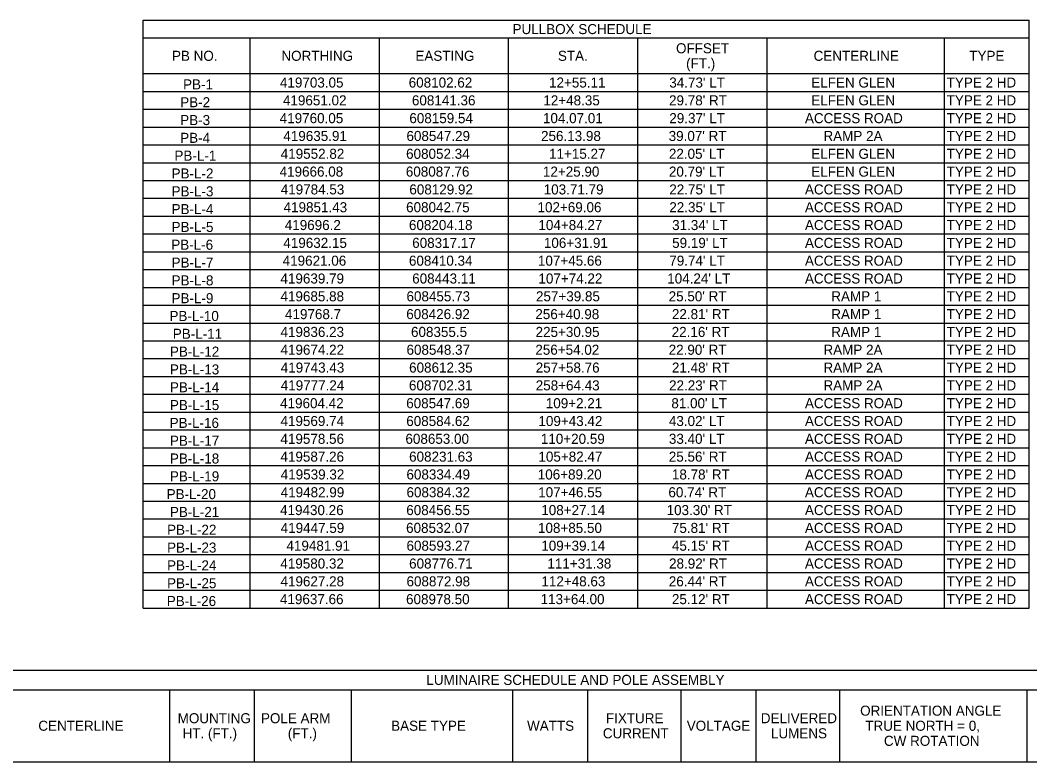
# Model space of a CAD drawing. Extents: x 0.17 to 2.79, y 0.05 to 1.72.
# Drawn here: x 0.862 to 1.859, y 0.976 to 1.708 of the extents above; entities that cross this region are included whole.
import ezdxf

# ---------------------------------------------------------------- set-up
doc = ezdxf.new("R2010")
doc.units = 0
doc.layers.add('Default', color=7, linetype='Continuous')
doc.layers.add('No_Plot', color=7, linetype='Continuous')

msp = doc.modelspace()

# ---------------------------------------------------------------- linework, layer by layer
at = {"layer": 'Default'}
for p, q in [((0.98367, 1.70829), (1.85833, 1.70829)), ((0.98367, 1.12753), (0.98367, 1.70829)), ((1.85833, 1.12753), (1.85833, 1.70829)), ((0.98367, 1.69069), (1.85833, 1.69069)), ((1.08927, 1.12753), (1.08927, 1.69069)), ((1.21686, 1.12753), (1.21686, 1.69069)), ((1.34445, 1.12753), (1.34445, 1.69069)), ((1.47204, 1.12753), (1.47204, 1.69069)), ((1.59963, 1.12753), (1.59963, 1.69069)), ((1.77474, 1.12753), (1.77474, 1.69069)), ((0.98367, 1.65549), (1.85833, 1.65549)), ((0.98367, 1.63789), (1.85833, 1.63789)), ((0.98367, 1.6203), (1.85833, 1.6203)), ((0.98367, 1.6027), (1.85833, 1.6027)), ((0.98367, 1.5851), (1.85833, 1.5851)), ((0.98367, 1.5675), (1.85833, 1.5675)), ((0.98367, 1.5499), (1.85833, 1.5499)), ((0.98367, 1.5323), (1.85833, 1.5323)), ((0.98367, 1.5147), (1.85833, 1.5147)), ((0.98367, 1.4971), (1.85833, 1.4971)), ((0.98367, 1.47951), (1.85833, 1.47951)), ((0.98367, 1.46191), (1.85833, 1.46191)), ((0.98367, 1.44431), (1.85833, 1.44431)), ((0.98367, 1.42671), (1.85833, 1.42671)), ((0.98367, 1.40911), (1.85833, 1.40911)), ((0.98367, 1.39151), (1.85833, 1.39151)), ((0.98367, 1.37391), (1.85833, 1.37391)), ((0.98367, 1.35631), (1.85833, 1.35631)), ((0.98367, 1.33872), (1.85833, 1.33872)), ((0.98367, 1.32112), (1.85833, 1.32112)), ((0.98367, 1.30352), (1.85833, 1.30352)), ((0.98367, 1.28592), (1.85833, 1.28592)), ((0.98367, 1.26832), (1.85833, 1.26832)), ((0.98367, 1.25072), (1.85833, 1.25072)), ((0.98367, 1.23312), (1.85833, 1.23312)), ((0.98367, 1.21552), (1.85833, 1.21552)), ((0.98367, 1.19793), (1.85833, 1.19793)), ((0.98367, 1.18033), (1.85833, 1.18033)), ((0.98367, 1.16273), (1.85833, 1.16273)), ((0.98367, 1.14513), (1.85833, 1.14513)), ((0.98367, 1.12753), (1.85833, 1.12753)), ((0.32609, 1.06625), (2.52066, 1.06625)), ((0.32609, 1.04689), (2.52066, 1.04689)), ((1.0098, 0.97562), (1.0098, 1.04689)), ((1.0934, 0.97562), (1.0934, 1.04689)), ((1.18931, 0.97562), (1.18931, 1.04689)), ((1.34858, 0.97562), (1.34858, 1.04689)), ((1.42249, 0.97562), (1.42249, 1.04689)), ((1.51489, 0.97562), (1.51489, 1.04689)), ((1.5888, 0.97562), (1.5888, 1.04689)), ((1.67152, 0.97562), (1.67152, 1.04689)), ((1.8563, 0.97562), (1.8563, 1.04689)), ((0.32609, 0.97562), (2.52066, 0.97562))]:
    msp.add_line(p, q, dxfattribs=at)
at = {"layer": 'No_Plot'}
msp.add_line((0.98367, 1.70829), (0.98367, 1.70829), dxfattribs=at)

# ---------------------------------------------------------------- texts
at = {"layer": 'Default'}
for s, height, p in [('PULLBOX SCHEDULE', 0.0099275, (1.34831, 1.69453)), ('OFFSET', 0.009927, (1.50969, 1.67557)), ('PB NO.', 0.009927, (1.01208, 1.66813)), ('NORTHING', 0.009927, (1.12011, 1.66813)), ('EASTING', 0.009927, (1.2524, 1.66813)), ('STA.', 0.009927, (1.39308, 1.66813)), ('CENTERLINE', 0.009927, (1.64552, 1.66813)), ('TYPE', 0.009927, (1.79918, 1.66813)), (' (FT.)', 0.009927, (1.51594, 1.66068)), ('PB-1', 0.009927, (1.02303, 1.63988)), ('419703.05', 0.009927, (1.11867, 1.64173)), ('608102.62', 0.009927, (1.24579, 1.64173)), ('12+55.11', 0.009927, (1.38432, 1.64173)), ("34.73' LT", 0.009927, (1.50304, 1.64173)), ('ELFEN GLEN', 0.009927, (1.64329, 1.64173)), ('TYPE 2 HD', 0.009927, (1.77686, 1.64173)), ('PB-2', 0.009927, (1.02021, 1.62228)), ('419651.02', 0.009927, (1.12164, 1.62413)), ('608141.36', 0.009927, (1.24896, 1.62413)), ('12+48.35', 0.009927, (1.3787, 1.62413)), ("29.78' RT", 0.009927, (1.50281, 1.62413)), ('ELFEN GLEN', 0.009927, (1.64329, 1.62413)), ('TYPE 2 HD', 0.009927, (1.77686, 1.62413)), ('PB-3', 0.009927, (1.02021, 1.60468)), ('419760.05', 0.009927, (1.11843, 1.60653)), ('608159.54', 0.009927, (1.24642, 1.60653)), ('104.07.01', 0.009927, (1.37831, 1.60653)), ("29.37' LT", 0.009927, (1.50304, 1.60653)), ('ACCESS ROAD', 0.0099275, (1.63696, 1.60653)), ('TYPE 2 HD', 0.009927, (1.77686, 1.60653)), ('PB-4', 0.009927, (1.02021, 1.58708)), ('419635.91', 0.009927, (1.12203, 1.58893)), ('608547.29', 0.009927, (1.24356, 1.58893)), ('256.13.98', 0.009927, (1.37643, 1.58893)), ("39.07' RT", 0.009927, (1.50242, 1.58893)), ('RAMP 2A', 0.009927, (1.65525, 1.58893)), ('TYPE 2 HD', 0.009927, (1.77686, 1.58893)), ('PB-L-1', 0.009927, (1.01451, 1.56948)), ('419552.82', 0.009927, (1.11945, 1.57134)), ('608052.34', 0.009927, (1.24321, 1.57134)), ('11+15.27', 0.009927, (1.38432, 1.57134)), ("22.05' LT", 0.009927, (1.50265, 1.57134)), ('ELFEN GLEN', 0.009927, (1.64329, 1.57134)), ('TYPE 2 HD', 0.009927, (1.77686, 1.57134)), ('PB-L-2', 0.009927, (1.01169, 1.55189)), ('419666.08', 0.009927, (1.11836, 1.55374)), ('608087.76', 0.009927, (1.24294, 1.55374)), ('12+25.90', 0.009927, (1.37827, 1.55374)), ("20.79' LT", 0.009927, (1.50265, 1.55374)), ('ELFEN GLEN', 0.009927, (1.64329, 1.55374)), ('TYPE 2 HD', 0.009927, (1.77686, 1.55374)), ('419784.53', 0.009927, (1.11945, 1.53614)), ('608129.92', 0.009927, (1.24642, 1.53614)), ('103.71.79', 0.009927, (1.37905, 1.53614)), ("22.75' LT", 0.009927, (1.50304, 1.53614)), ('ACCESS ROAD', 0.0099275, (1.63696, 1.53614)), ('TYPE 2 HD', 0.009927, (1.77686, 1.53614)), ('PB-L-3', 0.009927, (1.01169, 1.53429)), ('PB-L-4', 0.009927, (1.01169, 1.51669)), ('419851.43', 0.009927, (1.12226, 1.51854)), ('608042.75', 0.009927, (1.24321, 1.51854)), ('102+69.06', 0.009927, (1.37295, 1.51854)), ("22.35' LT", 0.009927, (1.50304, 1.51854)), ('ACCESS ROAD', 0.0099275, (1.63696, 1.51854)), ('TYPE 2 HD', 0.009927, (1.77686, 1.51854)), ('PB-L-5', 0.009927, (1.01169, 1.49909)), ('419696.2', 0.009927, (1.12344, 1.50094)), ('608204.18', 0.009927, (1.24602, 1.50094)), ('104+84.27', 0.009927, (1.37385, 1.50094)), ("31.34' LT", 0.009927, (1.50586, 1.50094)), ('ACCESS ROAD', 0.0099275, (1.63696, 1.50094)), ('TYPE 2 HD', 0.009927, (1.77686, 1.50094)), ('PB-L-6', 0.009927, (1.01142, 1.48149)), ('419632.15', 0.009927, (1.12203, 1.48334)), ('608317.17', 0.009927, (1.24923, 1.48334)), ('106+31.91', 0.009927, (1.37924, 1.48334)), ("59.19' LT", 0.009927, (1.50586, 1.48334)), ('ACCESS ROAD', 0.0099275, (1.63696, 1.48334)), ('TYPE 2 HD', 0.009927, (1.77686, 1.48334)), ('419621.06', 0.009927, (1.12136, 1.46574)), ('608410.34', 0.009927, (1.24602, 1.46574)), ('107+45.66', 0.009927, (1.37334, 1.46574)), ("79.74' LT", 0.009927, (1.50304, 1.46574)), ('ACCESS ROAD', 0.0099275, (1.63696, 1.46574)), ('TYPE 2 HD', 0.009927, (1.77686, 1.46574)), ('PB-L-7', 0.009927, (1.01169, 1.46389)), ('PB-L-8', 0.009927, (1.01169, 1.44629)), ('419639.79', 0.009927, (1.11918, 1.44814)), ('608443.11', 0.009927, (1.24923, 1.44814)), ('107+74.22', 0.009927, (1.37385, 1.44814)), ("104.24' LT", 0.009927, (1.50101, 1.44814)), ('ACCESS ROAD', 0.0099275, (1.63696, 1.44814)), ('TYPE 2 HD', 0.009927, (1.77686, 1.44814)), ('PB-L-9', 0.009927, (1.01165, 1.42869)), ('419685.88', 0.009927, (1.11921, 1.43055)), ('608455.73', 0.009927, (1.2436, 1.43055)), ('257+39.85', 0.009927, (1.37143, 1.43055)), ("25.50' RT", 0.009927, (1.50242, 1.43055)), ('RAMP 1', 0.009927, (1.66295, 1.43055)), ('TYPE 2 HD', 0.009927, (1.77686, 1.43055)), ('PB-L-10', 0.009927, (1.00962, 1.4111)), ('419768.7', 0.009927, (1.12367, 1.41295)), ('608426.92', 0.009927, (1.24337, 1.41295)), ('256+40.98', 0.009927, (1.3708, 1.41295)), ("22.81' RT", 0.009927, (1.50562, 1.41295)), ('RAMP 1', 0.009927, (1.66295, 1.41295)), ('TYPE 2 HD', 0.009927, (1.77686, 1.41295)), ('419836.23', 0.009927, (1.11921, 1.39535)), ('608355.5', 0.009927, (1.24806, 1.39535)), ('225+30.95', 0.009927, (1.37104, 1.39535)), ("22.16' RT", 0.009927, (1.50539, 1.39535)), ('TYPE 2 HD', 0.009927, (1.77686, 1.39535)), ('PB-L-11', 0.009927, (1.01286, 1.3935)), ('RAMP 1', 0.009927, (1.66295, 1.39535)), ('PB-L-12', 0.009927, (1.01005, 1.3759)), ('419674.22', 0.009927, (1.11921, 1.37775)), ('608548.37', 0.009927, (1.2436, 1.37775)), ('256+54.02', 0.009927, (1.3708, 1.37775)), ("22.90' RT", 0.009927, (1.50242, 1.37775)), ('RAMP 2A', 0.009927, (1.65525, 1.37775)), ('TYPE 2 HD', 0.009927, (1.77686, 1.37775)), ('PB-L-13', 0.009927, (1.01005, 1.3583)), ('419743.43', 0.009927, (1.11945, 1.36015)), ('608612.35', 0.009927, (1.24618, 1.36015)), ('257+58.76', 0.009927, (1.37115, 1.36015)), ("21.48' RT", 0.009927, (1.50562, 1.36015)), ('RAMP 2A', 0.009927, (1.65525, 1.36015)), ('TYPE 2 HD', 0.009927, (1.77686, 1.36015)), ('PB-L-14', 0.009927, (1.01005, 1.3407)), ('419777.24', 0.009927, (1.11945, 1.34255)), ('608702.31', 0.009927, (1.24602, 1.34255)), ('258+64.43', 0.009927, (1.37119, 1.34255)), ("22.23' RT", 0.009927, (1.50281, 1.34255)), ('RAMP 2A', 0.009927, (1.65525, 1.34255)), ('TYPE 2 HD', 0.009927, (1.77686, 1.34255)), ('PB-L-15', 0.009927, (1.01005, 1.3231)), ('419604.42', 0.009927, (1.11882, 1.32495)), ('608547.69', 0.009927, (1.24333, 1.32495)), ('109+2.21', 0.009927, (1.38112, 1.32495)), ("81.00' LT", 0.009927, (1.50508, 1.32495)), ('ACCESS ROAD', 0.0099275, (1.63696, 1.32495)), ('TYPE 2 HD', 0.009927, (1.77686, 1.32495)), ('419569.74', 0.009927, (1.11921, 1.30735)), ('608584.62', 0.009927, (1.24337, 1.30735)), ('109+43.42', 0.009927, (1.37385, 1.30735)), ("43.02' LT", 0.009927, (1.50265, 1.30735)), ('ACCESS ROAD', 0.0099275, (1.63696, 1.30735)), ('TYPE 2 HD', 0.009927, (1.77686, 1.30735)), ('PB-L-16', 0.009927, (1.00978, 1.3055)), ('PB-L-17', 0.009927, (1.01005, 1.2879)), ('419578.56', 0.009927, (1.11918, 1.28976)), ('608653.00', 0.009927, (1.24255, 1.28976)), ('110+20.59', 0.009927, (1.37623, 1.28976)), ("33.40' LT", 0.009927, (1.50265, 1.28976)), ('ACCESS ROAD', 0.0099275, (1.63696, 1.28976)), ('TYPE 2 HD', 0.009927, (1.77686, 1.28976)), ('PB-L-18', 0.009927, (1.01005, 1.27031)), ('419587.26', 0.009927, (1.11918, 1.27216)), ('608231.63', 0.009927, (1.24618, 1.27216)), ('105+82.47', 0.009927, (1.37385, 1.27216)), ("25.56' RT", 0.009927, (1.50257, 1.27216)), ('ACCESS ROAD', 0.0099275, (1.63696, 1.27216)), ('TYPE 2 HD', 0.009927, (1.77686, 1.27216)), ('PB-L-19', 0.009927, (1.01001, 1.25271)), ('419539.32', 0.009927, (1.11945, 1.25456)), ('608334.49', 0.009927, (1.24356, 1.25456)), ('106+89.20', 0.009927, (1.37319, 1.25456)), ("18.78' RT", 0.009927, (1.50562, 1.25456)), ('ACCESS ROAD', 0.0099275, (1.63696, 1.25456)), ('TYPE 2 HD', 0.009927, (1.77686, 1.25456)), ('419482.99', 0.009927, (1.11941, 1.23696)), ('608384.32', 0.009927, (1.2436, 1.23696)), ('107+46.55', 0.009927, (1.37362, 1.23696)), ("60.74' RT", 0.009927, (1.50218, 1.23696)), ('ACCESS ROAD', 0.0099275, (1.63696, 1.23696)), ('TYPE 2 HD', 0.009927, (1.77686, 1.23696)), ('PB-L-20', 0.009927, (1.00681, 1.23511)), ('PB-L-21', 0.009927, (1.01005, 1.21751)), ('419430.26', 0.009927, (1.11879, 1.21936)), ('608456.55', 0.009927, (1.24337, 1.21936)), ('108+27.14', 0.009927, (1.37666, 1.21936)), ("103.30' RT", 0.009927, (1.50039, 1.21936)), ('ACCESS ROAD', 0.0099275, (1.63696, 1.21936)), ('TYPE 2 HD', 0.009927, (1.77686, 1.21936)), ('PB-L-22', 0.009927, (1.00724, 1.19991)), ('419447.59', 0.009927, (1.11941, 1.20176)), ('608532.07', 0.009927, (1.24321, 1.20176)), ('108+85.50', 0.009927, (1.37342, 1.20176)), ("75.81' RT", 0.009927, (1.50562, 1.20176)), ('ACCESS ROAD', 0.0099275, (1.63696, 1.20176)), ('TYPE 2 HD', 0.009927, (1.77686, 1.20176)), ('PB-L-23', 0.009927, (1.00724, 1.18231)), ('419481.91', 0.009927, (1.12508, 1.18416)), ('608593.27', 0.009927, (1.2436, 1.18416)), ('109+39.14', 0.009927, (1.37666, 1.18416)), ("45.15' RT", 0.009927, (1.50562, 1.18416)), ('ACCESS ROAD', 0.0099275, (1.63696, 1.18416)), ('TYPE 2 HD', 0.009927, (1.77686, 1.18416)), ('419580.32', 0.009927, (1.11906, 1.16656)), ('608776.71', 0.009927, (1.24618, 1.16656)), ('111+31.38', 0.009927, (1.38268, 1.16656)), ("28.92' RT", 0.009927, (1.50281, 1.16656)), ('ACCESS ROAD', 0.0099275, (1.63696, 1.16656)), ('TYPE 2 HD', 0.009927, (1.77686, 1.16656)), ('PB-L-24', 0.009927, (1.00724, 1.16471)), ('PB-L-25', 0.009927, (1.00724, 1.14711)), ('419627.28', 0.009927, (1.11921, 1.14897)), ('608872.98', 0.009927, (1.2436, 1.14897)), ('112+48.63', 0.009927, (1.37682, 1.14897)), ("26.44' RT", 0.009927, (1.50257, 1.14897)), ('ACCESS ROAD', 0.0099275, (1.63696, 1.14897)), ('TYPE 2 HD', 0.009927, (1.77686, 1.14897)), ('PB-L-26', 0.009927, (1.00696, 1.12952)), ('419637.66', 0.009927, (1.11871, 1.13137)), ('608978.50', 0.009927, (1.24317, 1.13137)), ('113+64.00', 0.009927, (1.376, 1.13137)), ("25.12' RT", 0.009927, (1.50562, 1.13137)), ('ACCESS ROAD', 0.0099275, (1.63696, 1.13137)), ('TYPE 2 HD', 0.009927, (1.77686, 1.13137)), ('LUMINAIRE SCHEDULE AND POLE ASSEMBLY', 0.0099275, (1.26321, 1.05161)), ('ORIENTATION ANGLE', 0.0099275, (1.69145, 1.02118)), ('MOUNTING', 0.009927, (1.01771, 1.01374)), ('POLE ARM ', 0.009927, (1.09992, 1.01374)), ('FIXTURE', 0.009927, (1.44047, 1.01374)), ('DELIVERED', 0.009927, (1.59338, 1.01374)), ('CENTERLINE', 0.009927, (0.88015, 1.00629)), ('HT. (FT.)', 0.009927, (1.02252, 0.99885)), ('(FT.)', 0.009927, (1.12642, 0.99885)), ('BASE TYPE', 0.009927, (1.22845, 1.00629)), ('WATTS', 0.009927, (1.36263, 1.00629)), ('CURRENT', 0.009927, (1.43746, 0.99885)), ('VOLTAGE', 0.009927, (1.52027, 1.00629)), ('LUMENS', 0.009927, (1.60343, 0.99885)), ('TRUE NORTH = 0, ', 0.0099275, (1.69653, 1.00629)), ('CW ROTATION', 0.0099275, (1.71494, 0.9914))]:
    msp.add_text(s, height=height, dxfattribs=at).set_placement(p)

doc.saveas('drawing.dxf')
